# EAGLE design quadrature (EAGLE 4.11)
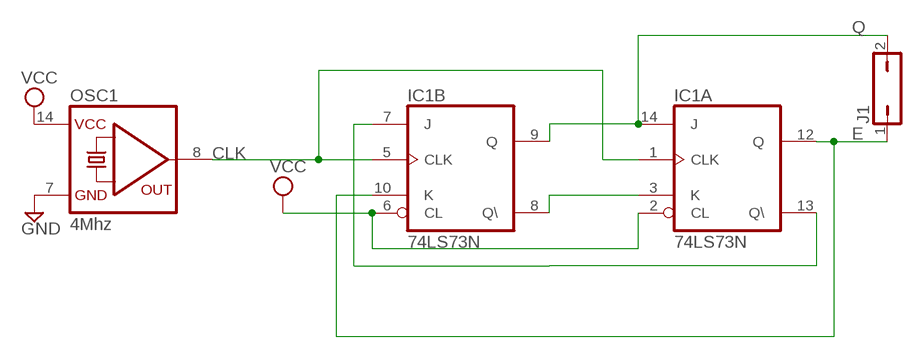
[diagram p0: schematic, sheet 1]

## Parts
IC1  74LS73N  [DIL14]
J1  JP1Q  [JP1]
OSC1  4Mhz  QG5860  [DIL14S]

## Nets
CLK: IC1.1(A:CLK) IC1.5(B:CLK) OSC1.8(OUT)
E: IC1.10(B:K) IC1.12(A:Q) J1.1
GND: OSC1.7(GND)
N$1: IC1.3(A:K) IC1.8(B:Q\)
N$2: IC1.7(B:J) IC1.13(A:Q\)
Q: IC1.9(B:Q) IC1.14(A:J) J1.2
VCC: IC1.2(A:CL) IC1.6(B:CL) OSC1.14(VCC)

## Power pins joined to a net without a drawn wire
GND: IC1.11(P:GND)
VCC: IC1.4(P:VCC)

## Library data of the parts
IC1 = 74xx-us:74*73: Dual J-K FLIP FLOP, clear
J1 = jumper:JP1Q: JUMPER
OSC1 = crystal:QG5860: CRYSTAL RESONATOR

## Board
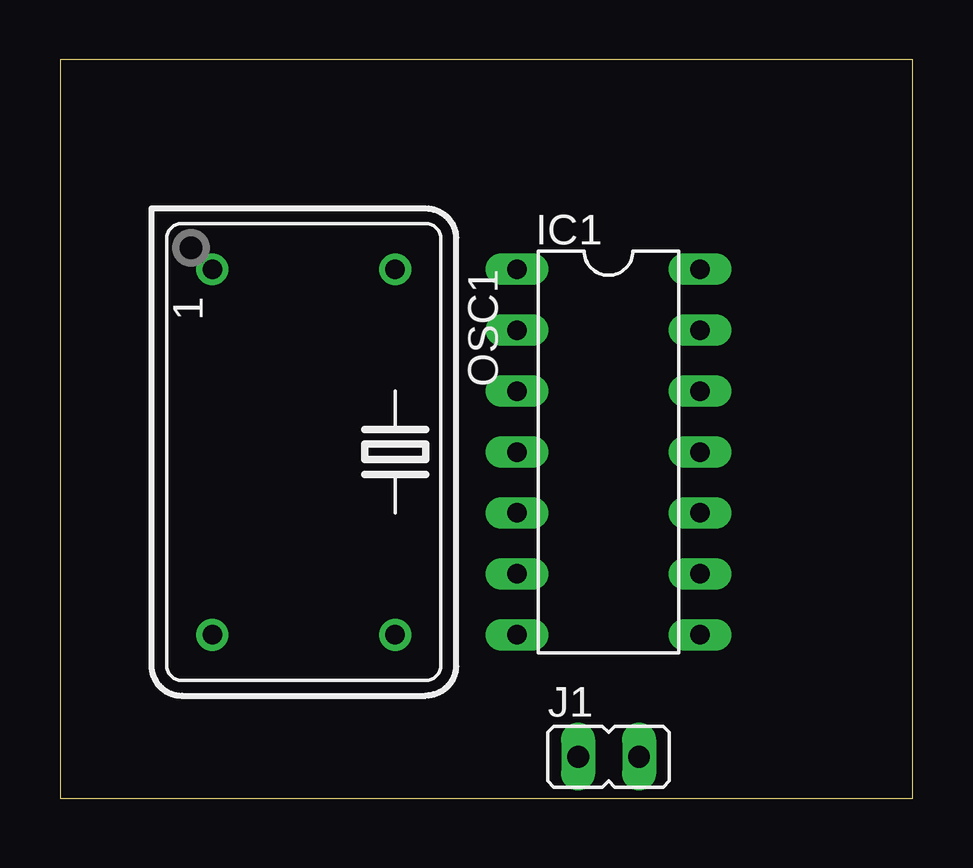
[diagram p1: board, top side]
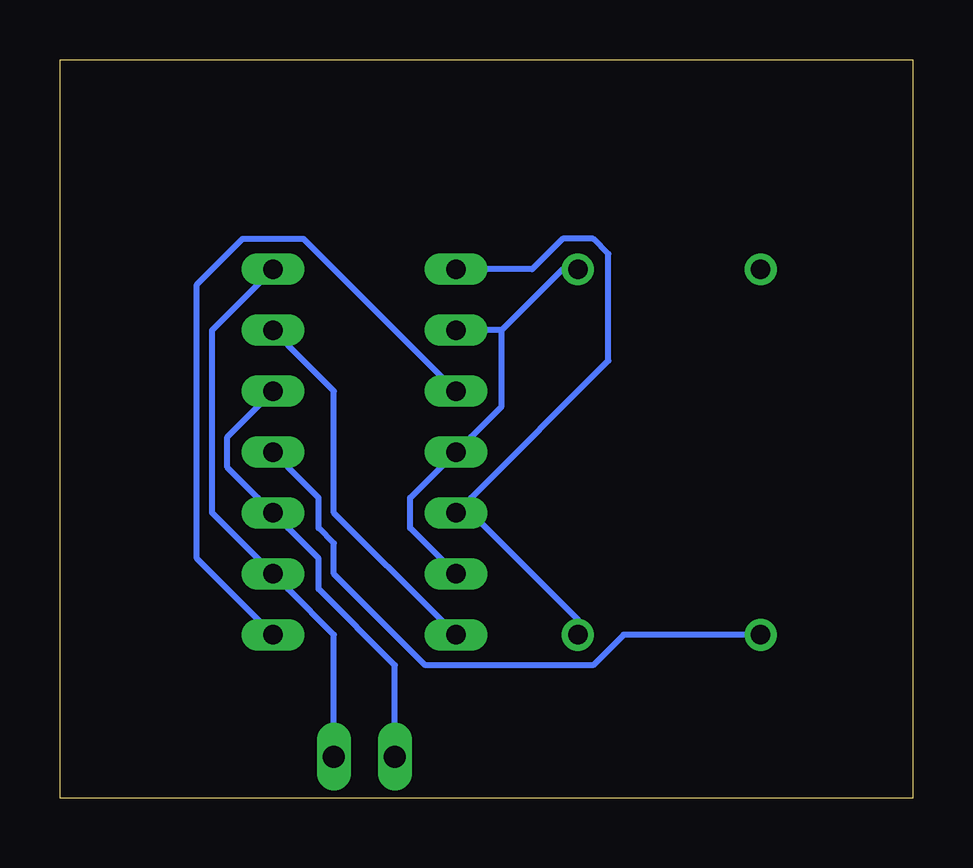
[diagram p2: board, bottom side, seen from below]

Size 35.54 x 30.79 mm. Coordinates in mm from the lower left corner, seen from the top.
Outline: 0,0 35.54,0 35.54,30.79 0,30.79 0,0
Copper layers (1*16): Top 0.035mm / dielectric 1.5mm / Bottom 0.035mm
Design rules "default": minimum track width 10mil, minimum drill 24mil, track to track 8mil, track to pad 8mil, pad to pad 8mil, via to via 8mil, smd to smd 8mil, copper to edge 40mil, drill to drill 8mil, minimum pad ring 10mil, minimum via ring 8mil, stop-mask expansion 4mil, vias tented up to drill 0mil, thermal gap 10mil

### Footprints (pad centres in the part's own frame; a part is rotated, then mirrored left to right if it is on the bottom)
DIL14 = drill 0.813 long: 1 -7.62,-3.81; 2 -5.08,-3.81; 3 -2.54,-3.81; 4 0,-3.81; 5 2.54,-3.81; 6 5.08,-3.81; 7 7.62,-3.81; 8 7.62,3.81; 9 5.08,3.81; 10 2.54,3.81; 11 0,3.81; 12 -2.54,3.81; 13 -5.08,3.81; 14 -7.62,3.81
JP1 = drill 0.914 long: 1 0,-1.27; 2 0,1.27
DIL14S = drill 0.813 round: 1 -7.62,-3.81; 7 7.62,-3.81; 8 7.62,3.81; 14 -7.62,3.81

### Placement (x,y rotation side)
IC1  22.86,14.44 270 top
J1  22.86,1.74 270 top
OSC1  10.15,14.44 270 top

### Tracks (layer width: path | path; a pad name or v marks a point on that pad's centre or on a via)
CLK
  Bottom 0.254: OSC1.8 13.96,7.46 18.41,11.9 IC1.5 18.41,12.54 12.69,18.25 12.69,22.7 13.33,23.33 14.6,23.33 15.87,22.06 17.78,22.06 IC1.1
E
  Bottom 0.254: IC1.12 27.3,16.34 28.57,15.08 28.57,13.81 27.3,12.54 IC1.10 26.03,11.27 24.76,10 24.76,8.73 21.59,5.55 21.59,3.01 J1.1
GND
  Bottom 0.254: OSC1.7 6.98,6.82 12.06,6.82 13.33,5.55 20.32,5.55 24.12,9.36 24.12,10.63 24.76,11.27 24.76,12.54 26.03,13.81 IC1.11
N$1
  Bottom 0.254: IC1.8 27.3,7.46 29.84,10 29.84,21.42 27.94,23.33 25.39,23.33 19.68,17.61 IC1.3
N$2
  Bottom 0.254: IC1.7 19.68,7.46 24.12,11.9 24.12,16.98 26.03,18.88 IC1.13
Q
  Bottom 0.254: J1.2 24.12,3.01 24.12,6.82 26.03,8.73 IC1.9 27.3,10 29.21,11.9 29.21,19.52 27.3,21.42 IC1.14
VCC
  Bottom 0.254: IC1.6 19.68,10 20.95,11.27 20.95,12.54 19.68,13.81 IC1.4 18.41,15.08 17.14,16.34 17.14,19.52 | 17.14,19.52 14.6,22.06 OSC1.14 | 17.14,19.52 17.78,19.52 IC1.2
